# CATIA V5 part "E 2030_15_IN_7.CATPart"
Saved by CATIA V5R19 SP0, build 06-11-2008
Material "Plastic": density 1200 kg/m3, Young's modulus 2.2e+09 Pa, Poisson ratio 0.38, thermal expansion 6.84e-05 1/K
Bounding box of the stored display mesh (mm): x 37.75 to 52.85, y -30.19 to -15.11, z -2 to 0
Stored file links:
  G:\UTB\Kombinované\Bakalářská práce\Catia\FORMA\E 2030_15_IN_7.CATPart
  D:\Aplikace\CATIA\Nová složka\win_b64\startup\materials\Catalog.CATMaterial
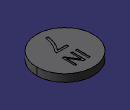
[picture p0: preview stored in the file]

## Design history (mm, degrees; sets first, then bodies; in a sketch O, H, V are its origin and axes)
Body1 "E 2030_15_IN_1-8" (main body)
  Solid1: solid without history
